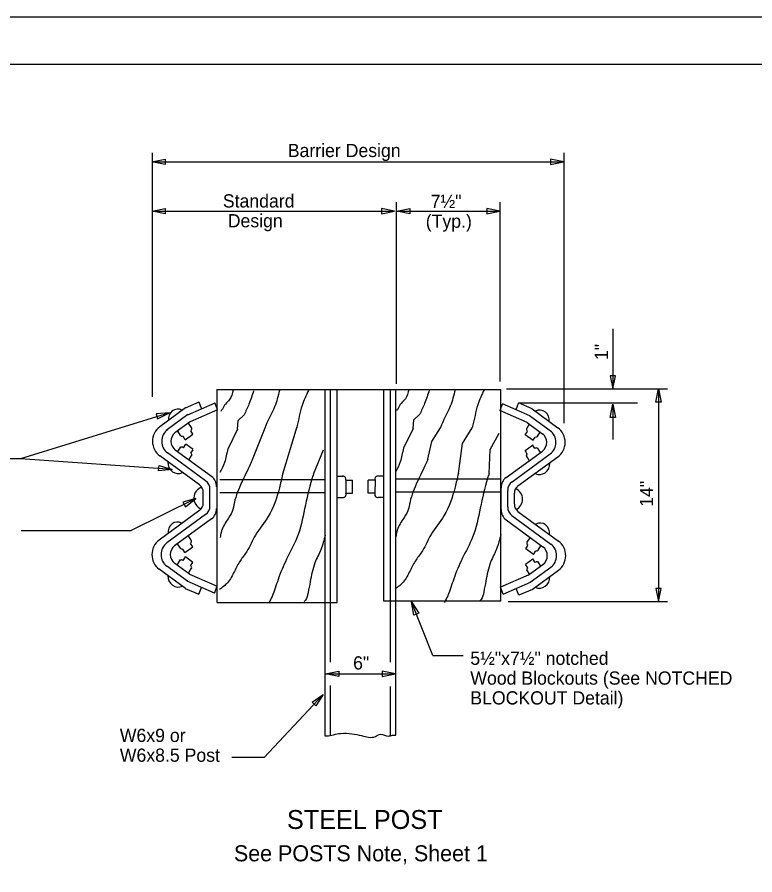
# Model space of a CAD drawing. Extents: x 0 to 34, y 0 to 22.
# Drawn here: x 11.31 to 19.13, y 12.91 to 22 of the extents above; entities that cross this region are included whole.
import ezdxf

# ---------------------------------------------------------------- set-up
doc = ezdxf.new("R2010")
doc.units = 0
for name, color, linetype in [('SH_Border', 7, 'Continuous'), ('SH_Cut_Line', 7, 'Continuous'), ('ST_Details', 7, 'Continuous'), ('ST_Text', 7, 'Continuous')]:
    doc.layers.add(name, color=color, linetype=linetype)

msp = doc.modelspace()

# ---------------------------------------------------------------- linework, layer by layer
at = {"layer": 'SH_Border'}
msp.add_lwpolyline([(1.5, 21.5), (33.5, 21.5), (33.5, 0.5), (1.5, 0.5)], close=True, dxfattribs=at)
at = {"layer": 'SH_Cut_Line'}
msp.add_lwpolyline([(0, 0), (34, 0), (34, 22), (0, 22)], close=True, dxfattribs=at)
at = {"layer": 'ST_Details'}
for p, q in [((13.4259, 18.0523), (16.4369, 18.0523)), ((13.4259, 18.0523), (13.4259, 15.7958)), ((14.5747, 15.7959), (14.5747, 18.0451)), ((14.6314, 15.7959), (14.6314, 18.0451)), ((14.7022, 15.7959), (14.7022, 18.0451)), ((15.1951, 15.8103), (15.1951, 18.0498)), ((15.2659, 15.8103), (15.2659, 18.0498)), ((15.3226, 15.8103), (15.3226, 18.0498)), ((16.4327, 18.0523), (16.4327, 15.8101)), ((13.0934, 17.8588), (13.2373, 17.9216)), ((13.1181, 17.7858), (13.4075, 17.9121)), ((13.2648, 17.8514), (13.2378, 17.9208)), ((13.4337, 17.8419), (13.4067, 17.9111)), ((16.5979, 17.8408), (16.6249, 17.9099)), ((16.7693, 17.8479), (16.6253, 17.9108)), ((13.0936, 17.8584), (12.8207, 17.6584)), ((13.1473, 17.7153), (13.4369, 17.8414)), ((16.7153, 17.7044), (16.4258, 17.8308)), ((16.4289, 17.8311), (16.4559, 17.9004)), ((16.7445, 17.7749), (16.455, 17.9013)), ((16.7689, 17.8476), (17.0419, 17.6476)), ((13.1206, 17.7873), (12.8906, 17.6186)), ((13.7153, 17.7866), (13.6529, 17.7259)), ((15.5069, 17.6391), (15.5152, 17.7331)), ((15.5775, 17.7938), (15.5152, 17.7331)), ((16.7419, 17.7764), (16.972, 17.6078)), ((13.1464, 17.7148), (12.9798, 17.5926)), ((13.1579, 17.6501), (13.1277, 17.6974)), ((13.6448, 17.6319), (13.6529, 17.7259)), ((13.9344, 17.6438), (13.8023, 17.3079)), ((14.2746, 17.6569), (14.124, 17.1549)), ((15.5069, 17.6391), (15.4059, 17.4329)), ((16.7105, 17.6414), (16.7406, 17.6888)), ((16.7162, 17.7039), (16.8829, 17.5818)), ((13.0421, 17.5676), (13.0129, 17.6133)), ((13.0908, 17.5211), (13.0677, 17.5574)), ((13.0906, 17.5216), (13.1732, 17.5801)), ((13.173, 17.5801), (13.1504, 17.6156)), ((13.6448, 17.6319), (13.5426, 17.4211)), ((16.7778, 17.5129), (16.6952, 17.5716)), ((16.6953, 17.5714), (16.7179, 17.6069)), ((16.7775, 17.5126), (16.8007, 17.5488)), ((16.8263, 17.5589), (16.8554, 17.6046)), ((13.0724, 17.4353), (13.097, 17.4739)), ((13.1755, 17.4163), (13.0969, 17.4738)), ((16.6929, 17.4076), (16.7715, 17.4651)), ((16.7959, 17.4266), (16.7713, 17.4653)), ((13.3074, 17.0864), (12.9035, 17.3809)), ((13.3706, 17.1314), (12.9859, 17.4118)), ((13.0124, 17.3949), (13.0441, 17.4449)), ((13.1514, 17.3778), (13.1752, 17.4153)), ((14.4498, 17.1549), (14.5582, 17.4138)), ((16.4919, 17.1208), (16.8766, 17.4011)), ((16.5551, 17.0758), (16.959, 17.3701)), ((16.717, 17.3691), (16.6931, 17.4068)), ((16.8559, 17.3863), (16.8242, 17.4363)), ((13.2443, 17.0414), (12.8211, 17.3499)), ((13.1304, 17.3089), (13.1614, 17.3574)), ((16.6184, 17.0308), (17.0415, 17.3391)), ((16.7379, 17.3003), (16.7069, 17.3489)), ((14.5702, 17.0973), (13.4582, 17.0973)), ((14.5761, 16.9008), (14.5761, 17.1333)), ((14.7007, 17.1346), (14.7691, 17.1346)), ((14.7929, 17.0938), (14.8656, 17.0938)), ((14.7929, 17.0938), (14.7939, 16.9536)), ((14.8656, 16.9536), (14.8656, 17.0938)), ((15.0303, 16.9536), (15.0303, 17.0928)), ((15.103, 17.0938), (15.0313, 17.0938)), ((15.103, 17.0938), (15.1019, 16.9536)), ((15.1952, 17.1346), (15.1269, 17.1346)), ((16.4324, 17.1043), (15.3204, 17.1043)), ((16.4384, 16.7801), (16.4384, 17.0126)), ((13.2826, 16.8499), (13.2826, 16.9643)), ((13.3534, 16.8206), (13.3534, 16.9938)), ((13.3534, 16.9018), (13.3534, 16.9126)), ((14.5702, 16.9571), (13.4579, 16.9571)), ((14.7007, 16.9101), (14.7603, 16.9101)), ((14.7939, 16.9536), (14.8656, 16.9536)), ((15.1019, 16.9536), (15.0303, 16.9536)), ((15.1952, 16.9101), (15.1356, 16.9101)), ((16.4324, 16.9641), (15.32, 16.9641)), ((16.5091, 16.8098), (16.5091, 16.9829)), ((16.5799, 16.8391), (16.5799, 16.9536)), ((16.5091, 16.8911), (16.5091, 16.9018)), ((13.2444, 16.7728), (12.8141, 16.4574)), ((13.3076, 16.7281), (12.8965, 16.4266)), ((16.6181, 16.7621), (17.0485, 16.4466)), ((13.3709, 16.6831), (12.9792, 16.3959)), ((16.4917, 16.6723), (16.8834, 16.3851)), ((16.5549, 16.7173), (16.966, 16.4158)), ((13.1555, 16.4554), (13.1254, 16.5028)), ((16.7162, 16.4349), (16.7463, 16.4823)), ((13.0397, 16.3728), (13.0106, 16.4184)), ((13.0883, 16.3268), (13.1708, 16.3854)), ((13.1707, 16.3853), (13.148, 16.4208)), ((16.7009, 16.3648), (16.7236, 16.4003)), ((16.7834, 16.3063), (16.7009, 16.3649)), ((16.8319, 16.3523), (16.861, 16.3979)), ((13.0884, 16.3264), (13.0653, 16.3628)), ((13.07, 16.2406), (13.0947, 16.2793)), ((13.1732, 16.2216), (13.0944, 16.2791)), ((16.7832, 16.3059), (16.8064, 16.3423)), ((13.1368, 16.0961), (12.9794, 16.2108)), ((13.01, 16.2003), (13.0418, 16.2503)), ((13.1489, 16.1831), (13.1729, 16.2206)), ((16.6985, 16.2011), (16.7772, 16.2586)), ((16.7227, 16.1626), (16.6988, 16.2001)), ((16.7258, 16.0853), (16.8832, 16.1999)), ((16.8016, 16.2201), (16.7769, 16.2588)), ((16.8616, 16.1798), (16.8299, 16.2298)), ((13.0939, 15.9451), (12.8144, 16.1488)), ((13.1147, 16.0211), (12.8969, 16.1798)), ((13.1281, 16.1141), (13.1591, 16.1628)), ((13.1368, 16.0964), (13.4305, 15.9684)), ((16.7435, 16.0936), (16.7126, 16.1423)), ((16.7479, 16.0103), (16.9657, 16.1689)), ((16.7687, 15.9343), (17.0481, 16.1379)), ((13.4025, 15.8953), (13.1131, 16.0216)), ((16.7258, 16.0856), (16.4321, 15.9576)), ((16.46, 15.8844), (16.7495, 16.0108)), ((13.0916, 15.9459), (13.2356, 15.8831)), ((13.2347, 15.8834), (13.263, 15.9561)), ((13.4017, 15.8953), (13.4304, 15.9689)), ((16.4609, 15.8844), (16.4322, 15.9581)), ((16.6279, 15.8728), (16.5995, 15.9453)), ((16.7709, 15.9351), (16.627, 15.8724)), ((13.4309, 15.7959), (14.7022, 15.7959)), ((14.5747, 14.3838), (14.5747, 15.7959)), ((14.6314, 15.1623), (14.6314, 15.7959)), ((16.4369, 15.8103), (15.1951, 15.8103)), ((15.2659, 15.1644), (15.2659, 15.8103)), ((15.3226, 14.3884), (15.3226, 15.8103)), ((14.6314, 14.3838), (14.6314, 14.9148)), ((15.2659, 14.3884), (15.2659, 14.9061))]:
    msp.add_line(p, q, dxfattribs=at)
for points in [[(15.6644, 17.3151), (15.7035, 17.5041), (15.7956, 17.6481)], [(15.9862, 17.1619), (16.0312, 17.4816), (16.1326, 17.6481)], [(16.312, 17.1619), (16.3224, 17.4173), (16.4204, 17.5908)]]:
    msp.add_lwpolyline(points, dxfattribs=at)
for centre, major_axis, start_param, end_param in [((13.0133, 17.7395), (0, -0.1065), 2.687211, 4.851441), ((16.8493, 17.7287), (0, -0.1065), 1.431744, 3.595974), ((12.9215, 17.5043), (0, -0.1875), 3.747084, 5.680264), ((13.142, 17.6377), (0, 0.0198), 3.70437, 5.352473), ((16.7264, 17.6291), (0, 0.0198), 0.930712, 2.578815), ((16.9411, 17.4935), (0, -0.1875), 0.602921, 2.536101), ((12.9838, 17.5044), (0, -0.15), 3.747137, 5.680324), ((13.0462, 17.5045), (0, -0.1125), 3.747102, 5.680297), ((13.0549, 17.5782), (0, -0.0195), 5.247458, 6.879592), ((16.8134, 17.5696), (0, -0.0195), 5.686779, 7.318912), ((16.8164, 17.4937), (0, -0.1125), 0.602888, 2.536083), ((16.8788, 17.4936), (0, -0.15), 0.602861, 2.536048), ((13.0566, 17.4217), (0, 0.021), 5.452301, 7.118326), ((13.1423, 17.3593), (0, 0.021), 4.196406, 5.73538), ((16.7261, 17.3507), (0, 0.021), 0.547805, 2.086779), ((16.8117, 17.4131), (0, 0.021), 5.448045, 7.11407), ((13.0165, 17.277), (0, -0.115), 4.640651, 6.714317), ((16.8461, 17.2662), (0, -0.115), 5.852054, 7.925719), ((13.3003, 17.0234), (0, 0.1312), 4.712389, 5.680267), ((14.7675, 17.1051), (0, -0.0298), 2.729343, 3.43401), ((14.7664, 17.1043), (0, 0.03), 4.35702, 6.237266), ((14.7675, 17.1051), (0, -0.0298), 1.431351, 1.439211), ((15.1296, 17.1043), (0, 0.03), 0.045919, 1.926166), ((15.1284, 17.1051), (0, -0.0298), 4.843974, 4.851834), ((15.1284, 17.1051), (0, -0.0298), 2.849176, 3.553842), ((16.5623, 17.0126), (0, 0.1312), 0.602918, 1.570796), ((13.2933, 16.9017), (0, -0.1171), 3.363241, 5.976631), ((13.1941, 16.9643), (0, 0.0937), 4.712389, 5.680377), ((13.2472, 16.9939), (0, 0.1125), 4.712389, 5.68034), ((16.6154, 16.9831), (0, 0.1125), 0.602846, 1.570796), ((16.6685, 16.9535), (0, 0.0937), 0.602808, 1.570796), ((16.5546, 16.8905), (0, -0.1192), 0.40519, 2.779828), ((14.7653, 16.9419), (0, -0.0326), 6.093782, 8.224205), ((15.1307, 16.9419), (0, -0.0326), 4.342165, 6.472589), ((13.1941, 16.8499), (0, -0.0937), 0.605563, 1.570796), ((13.2472, 16.8205), (0, -0.1125), 0.605651, 1.570796), ((16.6685, 16.8391), (0, -0.0937), 4.712389, 5.677623), ((13.3003, 16.7909), (0, -0.1312), 0.605566, 1.570796), ((16.5623, 16.7801), (0, -0.1312), 4.712389, 5.677619), ((16.6154, 16.8097), (0, -0.1125), 4.712389, 5.677535), ((13.0103, 16.5426), (0, -0.1065), 2.687211, 4.851441), ((16.8523, 16.5318), (0, -0.1065), 1.431744, 3.595974), ((12.9149, 16.3032), (0, -0.1875), 3.747091, 5.68028), ((13.1396, 16.443), (0, 0.0198), 3.70437, 5.352473), ((12.9772, 16.3033), (0, -0.15), 3.747115, 5.680355), ((13.0396, 16.3034), (0, -0.1125), 3.747102, 5.680258), ((13.0526, 16.3835), (0, -0.0195), 5.247458, 6.879592), ((16.732, 16.4225), (0, 0.0198), 0.930712, 2.578815), ((16.823, 16.2926), (0, -0.1125), 0.602927, 2.536083), ((16.8854, 16.2925), (0, -0.15), 0.602831, 2.53607), ((16.9477, 16.2924), (0, -0.1875), 0.602905, 2.536094), ((16.8191, 16.363), (0, -0.0195), 5.686779, 7.318912), ((13.0543, 16.227), (0, 0.021), 5.452301, 7.118326), ((13.1399, 16.1645), (0, 0.021), 4.196406, 5.73538), ((16.8174, 16.2065), (0, 0.021), 5.448045, 7.11407), ((16.7318, 16.144), (0, 0.021), 0.547805, 2.086779), ((13.0165, 16.0736), (0, -0.115), 4.640651, 6.714317), ((16.8461, 16.0628), (0, -0.115), 5.852054, 7.925719)]:
    msp.add_ellipse(centre, major_axis=major_axis, ratio=0.944544, start_param=start_param, end_param=end_param, dxfattribs=at)
for points in [[(13.5984, 18.0479), (13.5621, 17.9471), (13.5167, 17.8989), (13.4849, 17.8461), (13.4687, 17.8203)], [(13.8164, 18.0384), (13.7664, 17.8989), (13.7153, 17.7866)], [(14.0889, 18.0433), (14.0389, 17.8701), (13.9345, 17.6441), (13.9334, 17.6409)], [(14.3976, 18.0433), (14.3295, 17.8846), (14.275, 17.6586), (14.2704, 17.6409)], [(15.4607, 18.0551), (15.4244, 17.9543), (15.3789, 17.9061), (15.3472, 17.8533), (15.3309, 17.8274)], [(15.6786, 18.0456), (15.6287, 17.9061), (15.5775, 17.7938)], [(15.9511, 18.0504), (15.9011, 17.8773), (15.7967, 17.6513), (15.7956, 17.6481)], [(16.2599, 18.0504), (16.1918, 17.8918), (16.1373, 17.6658), (16.1326, 17.6481)], [(13.5438, 17.4258), (13.5259, 17.3509), (13.5076, 17.2788), (13.4577, 17.1731)], [(15.4059, 17.4329), (15.388, 17.3581), (15.3699, 17.2859), (15.3199, 17.1801)], [(13.8023, 17.3079), (13.7801, 17.2596), (13.6892, 17.0673), (13.6121, 16.8558), (13.5894, 16.7596), (13.5349, 16.6683), (13.4714, 16.5386), (13.4622, 16.4856)], [(15.6644, 17.3151), (15.6423, 17.2668), (15.5514, 17.0744), (15.4743, 16.8629), (15.4516, 16.7668), (15.3971, 16.6754), (15.3335, 16.5456), (15.3244, 16.4928)], [(14.124, 17.1549), (14.0889, 17.0096), (13.9709, 16.7068), (13.8346, 16.5096), (13.7437, 16.3366), (13.6756, 16.2404), (13.6121, 16.1251), (13.5394, 16.0049), (13.4531, 15.9328)], [(14.4498, 17.1549), (14.4339, 17.1058), (14.3567, 16.7884), (14.275, 16.4808), (14.166, 16.2549), (14.0752, 16.0384), (14.0116, 15.8606), (13.9754, 15.7886)], [(15.9862, 17.1619), (15.9511, 17.0168), (15.833, 16.7139), (15.6968, 16.5168), (15.6059, 16.3438), (15.5379, 16.2476), (15.4743, 16.1323), (15.4017, 16.0121), (15.3154, 15.9399)], [(16.312, 17.1619), (16.2962, 17.1129), (16.2189, 16.7956), (16.1373, 16.4879), (16.0283, 16.2621), (15.9374, 16.0456), (15.8739, 15.8678), (15.8376, 15.7958)], [(14.5747, 16.5096), (14.5294, 16.3559), (14.4657, 16.2164), (14.4159, 16.0144), (14.3931, 15.8991), (14.3659, 15.8221), (14.3522, 15.8078)], [(16.4369, 16.5168), (16.3916, 16.3629), (16.3279, 16.2236), (16.278, 16.0216), (16.2553, 15.9063), (16.2281, 15.8293), (16.2144, 15.8149)], [(14.5718, 14.3814), (14.5904, 14.3821), (14.7387, 14.4089), (14.8567, 14.4041), (14.9612, 14.3849), (15.1064, 14.3753), (15.1609, 14.3993), (15.2473, 14.3801), (15.2872, 14.3884), (15.3226, 14.3884)]]:
    msp.add_spline(points, degree=3, dxfattribs=at)
at = {"layer": 'ST_Text'}
for p, q in [((12.7395, 20.5613), (12.7396, 17.9771)), ((17.1033, 20.5613), (17.1033, 17.6954)), ((12.7375, 20.4668), (17.1033, 20.4668)), ((15.3279, 20.0393), (15.3279, 18.1129)), ((16.4267, 20.0393), (16.4267, 18.1371)), ((12.7392, 19.9448), (13.3174, 19.9448)), ((13.3174, 19.9448), (15.3108, 19.9448)), ((15.3335, 19.9448), (15.7013, 19.9448)), ((15.7013, 19.9448), (16.4267, 19.9448)), ((17.6235, 18.6954), (17.6235, 18.0599)), ((16.4961, 18.0599), (18.2021, 18.0599)), ((18.1076, 18.0599), (18.1076, 17.3543)), ((16.6253, 17.9108), (17.8835, 17.9108)), ((17.6235, 17.898), (17.6235, 17.523)), ((12.9517, 17.2058), (11.3451, 17.3181)), ((18.1076, 17.3543), (18.1076, 15.8053)), ((13.2029, 16.8991), (12.5176, 16.5574)), ((11.3526, 16.5574), (12.5176, 16.5574)), ((15.7161, 15.2344), (15.4891, 15.8023)), ((16.514, 15.8053), (18.2021, 15.8053)), ((15.7161, 15.2344), (16.037, 15.2344)), ((14.5747, 15.0409), (15.3199, 15.0409)), ((14.5784, 15.0409), (14.7659, 15.0409)), ((13.9296, 14.1546), (14.5539, 14.8194)), ((13.9296, 14.1546), (13.5869, 14.1546))]:
    msp.add_line(p, q, dxfattribs=at)
for points in [[(12.8775, 20.4388), (12.7375, 20.4668), (12.8775, 20.4948)], [(16.9633, 20.4388), (17.1033, 20.4668), (16.9633, 20.4948)], [(12.8792, 19.9168), (12.7392, 19.9448), (12.8792, 19.9728)], [(15.1708, 19.9168), (15.3108, 19.9448), (15.1708, 19.9728)], [(15.4735, 19.9168), (15.3335, 19.9448), (15.4735, 19.9728)], [(16.2867, 19.9168), (16.4267, 19.9448), (16.2867, 19.9728)], [(17.5955, 18.1999), (17.6235, 18.0599), (17.6515, 18.1999)], [(18.0796, 17.9199), (18.1076, 18.0599), (18.1356, 17.9199)], [(17.5955, 17.758), (17.6235, 17.898), (17.6515, 17.758)], [(12.799, 17.7419), (12.9258, 17.8074), (12.7835, 17.7958)], [(12.8154, 17.2483), (12.9517, 17.2058), (12.8096, 17.1926)], [(13.0924, 16.8087), (13.2029, 16.8991), (13.0661, 16.8581)], [(18.0796, 15.9453), (18.1076, 15.8053), (18.1356, 15.9453)], [(15.5156, 15.662), (15.4891, 15.8023), (15.5675, 15.683)], [(14.7184, 15.0129), (14.5784, 15.0409), (14.7184, 15.0689)], [(15.1799, 15.0129), (15.3199, 15.0409), (15.1799, 15.0689)], [(14.4366, 14.7382), (14.5539, 14.8194), (14.4768, 14.6993)]]:
    msp.add_lwpolyline(points, close=True, dxfattribs=at)
msp.add_lwpolyline([(12.9258, 17.8074), (11.3451, 17.3181), (11.0944, 17.3181)], dxfattribs=at)

# ---------------------------------------------------------------- texts
for s, height, p in [('Barrier Design', 0.14, (14.1781, 20.517)), ('Standard', 0.14, (13.49, 19.9824)), (' 7½"', 0.14, (15.6407, 19.9777)), (' Design', 0.14, (13.49, 19.7724)), ('(Typ.)', 0.14, (15.6407, 19.7677)), ('5½"x7½" notched', 0.14, (16.1131, 15.135)), ('6" ', 0.14, (14.8709, 15.0858)), ('Wood Blockouts (See NOTCHED', 0.14, (16.1131, 14.925)), ('BLOCKOUT Detail)', 0.14, (16.1131, 14.715)), ('W6x9 or', 0.14, (12.3979, 14.3177)), ('W6x8.5 Post', 0.14, (12.3979, 14.1077)), ('STEEL POST', 0.2, (14.1695, 13.3959)), ('See POSTS Note, Sheet 1', 0.17, (13.6075, 13.0526))]:
    msp.add_text(s, height=height, dxfattribs=at).set_placement(p)
for s, p in [('1" ', (17.5724, 18.3656)), ('14" ', (18.0502, 16.8101))]:
    msp.add_text(s, height=0.14, rotation=90, dxfattribs=at).set_placement(p)

doc.saveas('drawing.dxf')
